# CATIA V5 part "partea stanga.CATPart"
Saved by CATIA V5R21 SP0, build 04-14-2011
Part number: 2. 6 DOF ARM ASSEMBLY_sldprt_AllCATPart
Bounding box of the stored display mesh (mm): x 78.35 to 174.6, y 290.035 to 299.669, z 134.178 to 171.053
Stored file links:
  C:\Users\laurc\OneDrive\Desktop\Practica de cercetare\simulare prehensor\partea stanga.CATPart
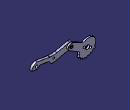
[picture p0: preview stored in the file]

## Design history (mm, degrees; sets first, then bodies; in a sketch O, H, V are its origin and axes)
Body1 (main body)
Body2 "2. 6 DOF ARM ASSEMBLY_sldprt.1"
  Solid1: solid without history
  Body3 "2. 6 DOF ARM ASSEMBLY_sldprt.1\\3. gear_link-2-solid1"
    Solid2 "Solid.1": solid without history
  Add1 "2. 6 DOF ARM ASSEMBLY_sldprt.1\\3. gear_link-2-solid1": tool Body3
  Body4 "2. 6 DOF ARM ASSEMBLY_sldprt.1\\pan cross head_am-70-solid1"
    Solid3 "Solid.1": solid without history
  Add2 "2. 6 DOF ARM ASSEMBLY_sldprt.1\\pan cross head_am-70-solid1": tool Body4
  Body5 "2. 6 DOF ARM ASSEMBLY_sldprt.1\\hex nut style 1_am-46-solid1"
    Solid4 "Solid.1": solid without history
  Add3 "2. 6 DOF ARM ASSEMBLY_sldprt.1\\hex nut style 1_am-46-solid1": tool Body5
